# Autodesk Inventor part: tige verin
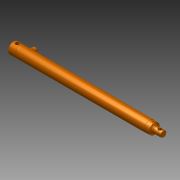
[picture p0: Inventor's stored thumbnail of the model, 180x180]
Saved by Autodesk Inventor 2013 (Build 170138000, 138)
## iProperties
Created: 2015-07
Part Number: tige verin
Material: Générique
Document SubType Name: Modeling
Designer: OL
Density: 1 g/cm^3
Norme de conversion: STEP AP203
Nom du fichier: 630.5.STEP
Préprocesseur: SolidWorks 2013
Postprocesseur: Build: 138, Release: 2013 RTM - Date: Thu 03/01/2012
Unités envoyées: millimètre
Incertitude: 1e-05
Author: OL
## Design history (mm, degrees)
node "630.51"
feature "Composite1"
body "Srf1"
